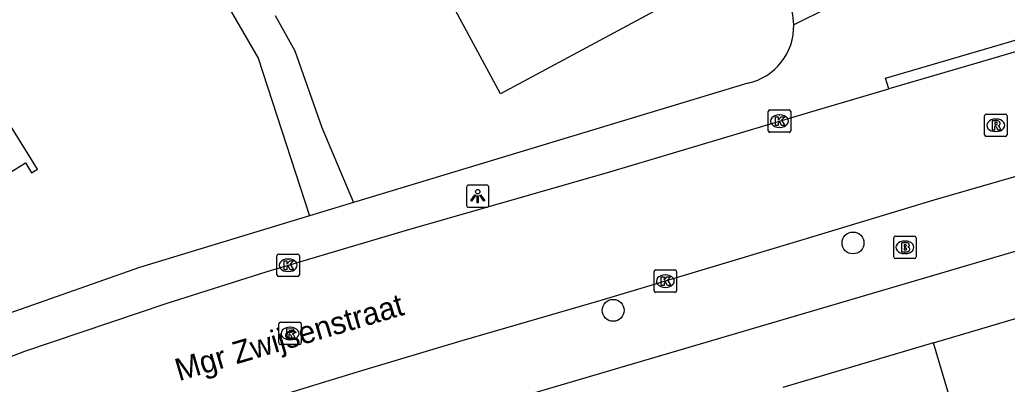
# Model space of a CAD drawing. Extents: x 162532 to 163264, y 381233 to 382042.
# Drawn here: x 162761.54 to 162805.65, y 381791.07 to 381807.38 of the extents above; entities that cross this region are included whole.
import ezdxf

# ---------------------------------------------------------------- set-up
doc = ezdxf.new("R2010")
doc.units = 0
for name, color, linetype in [('IMGEO_Boom', 7, 'Continuous'), ('IMGEO_Brandkraan', 7, 'Continuous'), ('IMGEO_Kolk', 7, 'Continuous'), ('IMGEO_Lichtpunt', 7, 'Continuous'), ('IMGEO_Openbare_ruimte_label', 7, 'Continuous'), ('IMGEO_Pand', 7, 'Continuous'), ('IMGEO_Rijbaan_lokaal_open', 7, 'Continuous'), ('IMGEO_Rioolput', 7, 'Continuous'), ('IMGEO_Voetpad_open', 7, 'Continuous')]:
    doc.layers.add(name, color=color, linetype=linetype)

msp = doc.modelspace()

# ---------------------------------------------------------------- linework, layer by layer
at = {"layer": 'IMGEO_Boom'}
for centre in [(162798.76, 381797.395), (162788.047, 381794.379)]:
    msp.add_circle(centre, 0.489, dxfattribs=at)
at = {"layer": 'IMGEO_Brandkraan'}
for p, q in [((162800.652, 381797.699), (162801.504, 381797.699)), ((162800.577, 381796.773), (162800.577, 381797.625)), ((162801.065, 381797.479), (162801.09, 381797.479)), ((162801.578, 381797.625), (162801.578, 381796.773)), ((162801.088, 381796.919), (162801.063, 381796.919)), ((162801.504, 381796.699), (162800.652, 381796.699))]:
    msp.add_line(p, q, dxfattribs=at)
for points in [[(162800.652, 381797.699), (162801.504, 381797.699)], [(162800.577, 381796.773), (162800.577, 381797.625)], [(162800.925, 381797.399), (162800.925, 381796.999), (162801.138, 381796.999)], [(162801.156, 381797.399), (162800.925, 381797.399)], [(162801.104, 381797.318), (162801.05, 381797.318), (162801.05, 381797.242)], [(162801.05, 381797.242), (162801.103, 381797.242)], [(162801.578, 381797.625), (162801.578, 381796.773)], [(162801.112, 381797.166), (162801.05, 381797.166), (162801.05, 381797.085)], [(162801.05, 381797.085), (162801.112, 381797.085)], [(162801.504, 381796.699), (162800.652, 381796.699)]]:
    msp.add_lwpolyline(points, dxfattribs=at)
for centre, radius, start, end in [((162800.654, 381797.623), 0.0765, 91.552, 178.448), ((162800.654, 381797.623), 0.0765, 91.552, 178.448), ((162801.502, 381797.623), 0.0765, 1.552, 88.448), ((162801.502, 381797.623), 0.0765, 1.552, 88.448), ((162801.105, 381797.28), 0.0379, 267.8285, 90.9355), ((162801.16, 381797.254), 0.145, 59.4692, 91.5367), ((162801.185, 381797.301), 0.0922, 285.5137, 58.1501), ((162801.113, 381797.125), 0.0404, 269.8759, 90.5077), ((162801.144, 381797.25), 0.251, 268.6676, 293.5347), ((162801.19, 381797.109), 0.105, 301.3115, 78.989), ((162800.654, 381796.775), 0.0765, 181.552, 268.448), ((162800.654, 381796.775), 0.0765, 181.552, 268.448), ((162801.502, 381796.775), 0.0765, 271.552, 358.448), ((162801.502, 381796.775), 0.0765, 271.552, 358.448)]:
    msp.add_arc(centre, radius, start, end, dxfattribs=at)
for centre, major_axis, ratio, start_param, end_param in [((162801.064, 381797.199), (-0.387, 0.002), 0.722429, 4.712389, 7.853982), ((162801.089, 381797.199), (-0.39, 0.002), 0.717154, 1.570796, 4.712389)]:
    msp.add_ellipse(centre, major_axis=major_axis, ratio=ratio, start_param=start_param, end_param=end_param, dxfattribs=at)
at = {"layer": 'IMGEO_Kolk'}
for p, q in [((162794.977, 381802.417), (162794.977, 381803.269)), ((162795.052, 381803.343), (162795.904, 381803.343)), ((162795.465, 381803.123), (162795.49, 381803.123)), ((162795.978, 381803.269), (162795.978, 381802.417)), ((162795.488, 381802.563), (162795.463, 381802.563)), ((162795.904, 381802.343), (162795.052, 381802.343)), ((162773.031, 381795.97), (162773.031, 381796.822)), ((162773.106, 381796.896), (162773.958, 381796.896)), ((162774.032, 381796.822), (162774.032, 381795.97)), ((162773.519, 381796.676), (162773.544, 381796.676)), ((162773.542, 381796.116), (162773.517, 381796.116)), ((162789.877, 381795.26), (162789.877, 381796.112)), ((162789.952, 381796.186), (162790.804, 381796.186)), ((162790.365, 381795.966), (162790.39, 381795.966)), ((162790.878, 381796.112), (162790.878, 381795.26)), ((162773.958, 381795.896), (162773.106, 381795.896)), ((162790.804, 381795.186), (162789.952, 381795.186)), ((162790.388, 381795.406), (162790.363, 381795.406))]:
    msp.add_line(p, q, dxfattribs=at)
for points in [[(162794.977, 381802.417), (162794.977, 381803.269)], [(162795.052, 381803.343), (162795.904, 381803.343)], [(162795.298, 381803.043), (162795.421, 381803.043), (162795.421, 381802.892), (162795.551, 381803.043), (162795.715, 381803.043), (162795.569, 381802.892), (162795.722, 381802.643), (162795.57, 381802.643), (162795.485, 381802.807), (162795.421, 381802.74), (162795.421, 381802.643), (162795.298, 381802.643), (162795.298, 381803.043)], [(162795.978, 381803.269), (162795.978, 381802.417)], [(162795.904, 381802.343), (162795.052, 381802.343)], [(162773.031, 381795.97), (162773.031, 381796.822)], [(162773.106, 381796.896), (162773.958, 381796.896)], [(162774.032, 381796.822), (162774.032, 381795.97)], [(162773.352, 381796.596), (162773.475, 381796.596), (162773.475, 381796.445), (162773.605, 381796.596), (162773.769, 381796.596), (162773.623, 381796.445), (162773.776, 381796.196), (162773.624, 381796.196), (162773.539, 381796.36), (162773.475, 381796.293), (162773.475, 381796.196), (162773.352, 381796.196), (162773.352, 381796.596)], [(162789.877, 381795.26), (162789.877, 381796.112)], [(162789.952, 381796.186), (162790.804, 381796.186)], [(162790.878, 381796.112), (162790.878, 381795.26)], [(162773.958, 381795.896), (162773.106, 381795.896)], [(162790.198, 381795.886), (162790.321, 381795.886), (162790.321, 381795.735), (162790.451, 381795.886), (162790.615, 381795.886), (162790.469, 381795.735), (162790.622, 381795.486), (162790.47, 381795.486), (162790.385, 381795.65), (162790.321, 381795.583), (162790.321, 381795.486), (162790.198, 381795.486), (162790.198, 381795.886)], [(162790.804, 381795.186), (162789.952, 381795.186)]]:
    msp.add_lwpolyline(points, dxfattribs=at)
for centre, start, end in [((162795.054, 381803.267), 91.552, 178.448), ((162795.054, 381803.267), 91.552, 178.448), ((162795.902, 381803.267), 1.552, 88.448), ((162795.902, 381803.267), 1.552, 88.448), ((162795.054, 381802.419), 181.552, 268.448), ((162795.054, 381802.419), 181.552, 268.448), ((162795.902, 381802.419), 271.552, 358.448), ((162795.902, 381802.419), 271.552, 358.448), ((162773.108, 381796.82), 91.552, 178.448), ((162773.108, 381796.82), 91.552, 178.448), ((162773.956, 381796.82), 1.552, 88.448), ((162773.956, 381796.82), 1.552, 88.448), ((162773.108, 381795.972), 181.552, 268.448), ((162773.108, 381795.972), 181.552, 268.448), ((162773.956, 381795.972), 271.552, 358.448), ((162773.956, 381795.972), 271.552, 358.448), ((162789.954, 381796.11), 91.552, 178.448), ((162789.954, 381796.11), 91.552, 178.448), ((162790.802, 381796.11), 1.552, 88.448), ((162790.802, 381796.11), 1.552, 88.448), ((162789.954, 381795.262), 181.552, 268.448), ((162789.954, 381795.262), 181.552, 268.448), ((162790.802, 381795.262), 271.552, 358.448), ((162790.802, 381795.262), 271.552, 358.448)]:
    msp.add_arc(centre, 0.0765, start, end, dxfattribs=at)
for centre, major_axis, ratio, start_param, end_param in [((162795.464, 381802.843), (-0.387, 0.002), 0.722429, 4.712389, 7.853982), ((162795.489, 381802.843), (-0.39, 0.002), 0.717154, 1.570796, 4.712389), ((162773.518, 381796.396), (-0.387, 0.002), 0.722429, 4.712389, 7.853982), ((162773.543, 381796.396), (-0.39, 0.002), 0.717154, 1.570796, 4.712389), ((162790.364, 381795.686), (-0.387, 0.002), 0.722429, 4.712389, 7.853982), ((162790.389, 381795.686), (-0.39, 0.002), 0.717154, 1.570796, 4.712389)]:
    msp.add_ellipse(centre, major_axis=major_axis, ratio=ratio, start_param=start_param, end_param=end_param, dxfattribs=at)
at = {"layer": 'IMGEO_Lichtpunt'}
for p, q in [((162781.5, 381799.89), (162781.5, 381799.083)), ((162781.5, 381799.89), (162781.5, 381799.083)), ((162782.402, 381799.985), (162781.594, 381799.985)), ((162782.402, 381799.985), (162781.594, 381799.985)), ((162782.496, 381799.083), (162782.496, 381799.89)), ((162782.496, 381799.083), (162782.496, 381799.89)), ((162781.594, 381798.989), (162782.402, 381798.989)), ((162781.594, 381798.989), (162782.402, 381798.989))]:
    msp.add_line(p, q, dxfattribs=at)
for points in [[(162781.874, 381799.554), (162781.913, 381799.526), (162781.725, 381799.264), (162781.687, 381799.291), (162781.874, 381799.554)], [(162781.976, 381799.506), (162782.023, 381799.506), (162782.023, 381799.184), (162781.976, 381799.184), (162781.976, 381799.506)], [(162782.086, 381799.526), (162782.124, 381799.553), (162782.311, 381799.291), (162782.272, 381799.263), (162782.086, 381799.526)]]:
    msp.add_lwpolyline(points, dxfattribs=at)
msp.add_circle((162781.999, 381799.688), 0.0994, dxfattribs=at)
for centre, start, end in [((162781.594, 381799.89), 90, 180), ((162781.594, 381799.89), 90, 180), ((162782.402, 381799.89), 0, 90), ((162782.402, 381799.89), 0, 90), ((162781.594, 381799.083), 180, 270), ((162781.594, 381799.083), 180, 270), ((162782.402, 381799.083), 270, 0), ((162782.402, 381799.083), 270, 360)]:
    msp.add_arc(centre, 0.0946, start, end, dxfattribs=at)
at = {"layer": 'IMGEO_Pand'}
for points in [[(162791.67, 381813.368), (162791.781, 381813.161), (162791.549, 381813.036), (162791.362, 381813.383), (162789.415, 381812.336), (162791.272, 381808.884), (162791.546, 381809.031), (162791.702, 381808.74), (162783.018, 381804.07), (162780.697, 381808.385), (162784.149, 381810.242), (162781.063, 381815.98)], [(162751.474, 381802.93), (162755.508, 381796.448), (162755.779, 381796.619), (162755.502, 381797.058), (162761.793, 381800.972), (162762.068, 381800.531), (162762.339, 381800.7), (162758.304, 381807.184)], [(162802.348, 381792.923), (162809.339, 381794.995)], [(162802.348, 381792.923), (162795.632, 381790.933)], [(162805.479, 381782.356), (162804.671, 381785.084), (162802.348, 381792.923)]]:
    msp.add_lwpolyline(points, dxfattribs=at)
at = {"layer": 'IMGEO_Rijbaan_lokaal_open'}
for points in [[(162862.173, 381816.941), (162854.633, 381814.666), (162832.068, 381808.004), (162819.812, 381804.396), (162808.82, 381801.17), (162802.377, 381799.307), (162796.363, 381797.487), (162787.489, 381794.819), (162781.286, 381793.023), (162776.799, 381791.68), (162772.813, 381790.449), (162769.038, 381789.246), (162766.727, 381788.461), (162755.484, 381784.46), (162743.537, 381780.118), (162727.812, 381774.435), (162715.816, 381770.216), (162710.603, 381768.297)], [(162807.475, 381806.37), (162804.287, 381805.438), (162800.354, 381804.283)], [(162750.568, 381788.41), (162754.947, 381789.947), (162761.762, 381792.555), (162768.08, 381794.68), (162772.588, 381796.113), (162778.822, 381797.969), (162787.905, 381800.573), (162796.87, 381803.259), (162800.354, 381804.283)]]:
    msp.add_lwpolyline(points, dxfattribs=at)
at = {"layer": 'IMGEO_Rioolput'}
for p, q in [((162804.637, 381802.232), (162804.637, 381803.084)), ((162804.712, 381803.158), (162805.564, 381803.158)), ((162805.638, 381803.084), (162805.638, 381802.232)), ((162805.125, 381802.938), (162805.15, 381802.938)), ((162805.564, 381802.158), (162804.712, 381802.158)), ((162805.148, 381802.378), (162805.123, 381802.378)), ((162773.113, 381792.92), (162773.113, 381793.772)), ((162773.188, 381793.846), (162774.04, 381793.846)), ((162774.114, 381793.772), (162774.114, 381792.92)), ((162773.601, 381793.626), (162773.626, 381793.626)), ((162774.04, 381792.846), (162773.188, 381792.846)), ((162773.624, 381793.066), (162773.599, 381793.066))]:
    msp.add_line(p, q, dxfattribs=at)
for points in [[(162804.637, 381802.232), (162804.637, 381803.084)], [(162804.712, 381803.158), (162805.564, 381803.158)], [(162805.638, 381803.084), (162805.638, 381802.232)], [(162805.226, 381802.856), (162804.974, 381802.858), (162804.974, 381802.458)], [(162804.974, 381802.458), (162805.098, 381802.458), (162805.098, 381802.62), (162805.109, 381802.62)], [(162805.152, 381802.777), (162805.098, 381802.777), (162805.098, 381802.696)], [(162805.098, 381802.696), (162805.15, 381802.696)], [(162805.156, 381802.591), (162805.227, 381802.458), (162805.367, 381802.458), (162805.302, 381802.584)], [(162805.564, 381802.158), (162804.712, 381802.158)], [(162773.113, 381792.92), (162773.113, 381793.772)], [(162773.188, 381793.846), (162774.04, 381793.846)], [(162774.114, 381793.772), (162774.114, 381792.92)], [(162773.702, 381793.544), (162773.45, 381793.546), (162773.45, 381793.146)], [(162773.45, 381793.146), (162773.574, 381793.146), (162773.574, 381793.308), (162773.585, 381793.308)], [(162773.628, 381793.465), (162773.574, 381793.465), (162773.574, 381793.384)], [(162773.574, 381793.384), (162773.626, 381793.384)], [(162773.632, 381793.279), (162773.703, 381793.146), (162773.843, 381793.146), (162773.778, 381793.272)], [(162774.04, 381792.846), (162773.188, 381792.846)]]:
    msp.add_lwpolyline(points, dxfattribs=at)
for centre, radius, start, end in [((162804.714, 381803.082), 0.0765, 91.552, 178.448), ((162804.714, 381803.082), 0.0765, 91.552, 178.448), ((162805.562, 381803.082), 0.0765, 1.552, 88.448), ((162805.562, 381803.082), 0.0765, 1.552, 88.448), ((162805.108, 381802.567), 0.0533, 26.0293, 88.6989), ((162805.134, 381802.885), 0.19, 274.7715, 282.9687), ((162805.158, 381802.681), 0.0964, 77.0061, 93.1865), ((162805.172, 381802.738), 0.0378, 276.6634, 79.6772), ((162805.225, 381802.746), 0.109, 350.3612, 89.416), ((162805.223, 381802.746), 0.112, 277.5842, 350.9817), ((162805.207, 381802.531), 0.108, 29.5134, 73.7905), ((162804.714, 381802.234), 0.0765, 181.552, 268.448), ((162804.714, 381802.234), 0.0765, 181.552, 268.448), ((162805.562, 381802.234), 0.0765, 271.552, 358.448), ((162805.562, 381802.234), 0.0765, 271.552, 358.448), ((162773.19, 381793.77), 0.0765, 91.552, 178.448), ((162773.19, 381793.77), 0.0765, 91.552, 178.448), ((162774.038, 381793.77), 0.0765, 1.552, 88.448), ((162774.038, 381793.77), 0.0765, 1.552, 88.448), ((162773.584, 381793.255), 0.0533, 26.0293, 88.6989), ((162773.61, 381793.573), 0.19, 274.7715, 282.9687), ((162773.634, 381793.369), 0.0964, 77.0061, 93.1865), ((162773.648, 381793.426), 0.0378, 276.6634, 79.6772), ((162773.701, 381793.434), 0.109, 350.3612, 89.416), ((162773.699, 381793.434), 0.112, 277.5842, 350.9817), ((162773.683, 381793.219), 0.108, 29.5134, 73.7905), ((162773.19, 381792.922), 0.0765, 181.552, 268.448), ((162773.19, 381792.922), 0.0765, 181.552, 268.448), ((162774.038, 381792.922), 0.0765, 271.552, 358.448), ((162774.038, 381792.922), 0.0765, 271.552, 358.448)]:
    msp.add_arc(centre, radius, start, end, dxfattribs=at)
for centre, major_axis, ratio, start_param, end_param in [((162805.124, 381802.658), (-0.387, 0.002), 0.722429, 4.712389, 7.853982), ((162805.149, 381802.658), (-0.39, 0.002), 0.717154, 1.570796, 4.712389), ((162773.6, 381793.346), (-0.387, 0.002), 0.722429, 4.712389, 7.853982), ((162773.625, 381793.346), (-0.39, 0.002), 0.717154, 1.570796, 4.712389)]:
    msp.add_ellipse(centre, major_axis=major_axis, ratio=ratio, start_param=start_param, end_param=end_param, dxfattribs=at)
at = {"layer": 'IMGEO_Voetpad_open'}
for points in [[(162775.329, 381784.916), (162774.54, 381787.759), (162837.328, 381806.26), (162860.416, 381813.203)], [(162769.657, 381810.036), (162772.186, 381805.655), (162774.478, 381798.601)], [(162799.119, 381808.655), (162796.115, 381807.158)], [(162772.957, 381807.575), (162773.831, 381805.989), (162775.038, 381802.563), (162776.456, 381799.2)], [(162800.354, 381804.283), (162800.213, 381804.761), (162807.334, 381806.849), (162807.475, 381806.37)], [(162794.067, 381804.538), (162776.456, 381799.2)], [(162776.456, 381799.2), (162774.478, 381798.601)], [(162774.478, 381798.601), (162766.887, 381796.3), (162753.849, 381791.703), (162752.202, 381794.074)]]:
    msp.add_lwpolyline(points, dxfattribs=at)
for centre, radius, start, end in [((162793.484, 381807.108), 2.631, 1.084, 27.1291), ((162793.482, 381807.105), 2.633, 282.828, 1.144)]:
    msp.add_arc(centre, radius, start, end, dxfattribs=at)

# ---------------------------------------------------------------- texts
at = {"layer": 'IMGEO_Openbare_ruimte_label'}
msp.add_text('Mgr Zwijsenstraat', height=1, rotation=16.4413, dxfattribs=at).set_placement((162768.654, 381791.209))

doc.saveas('drawing.dxf')
